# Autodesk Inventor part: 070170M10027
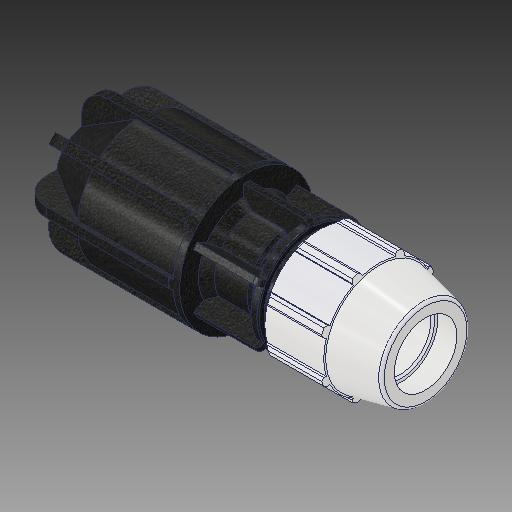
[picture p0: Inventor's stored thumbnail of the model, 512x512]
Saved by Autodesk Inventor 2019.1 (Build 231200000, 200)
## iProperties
Created: 2017-02
Part Number: 070170M10027
Material: PVC-Piping
Description: PLASSON PLASS4 COUPLING 1'' - 0.925
Document SubType Name: Modeling
Designer: KIM
Mass: 92.6774 g
Surface Area: 199.44 cm^2
Volume: 66.1981 cm^3
Density: 1.4 g/cm^3
Appearance: PTFE
Author: KIM
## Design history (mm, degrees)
derived "070170M0.ipt"
feature "Solid1::070170M0.ipt"
tag "TaggingFeature1"
body "Solid1"
other parameters: "d_" = 33.3, "E_" = 62.992, "A_" = 81, "l_" = 70.104, "d_1" = 23.495, "E_1" = 71.12, "l_1" = 85.09, "H_" = 180.086, "d106" = 40.02789, "d2" = 33.3, "d4" = 12.86329, "d5" = 24.5364, "d7" = 62.992, "d8" = 40.02789, "d9" = 11.57143, "d11" = 4.50215, "d12" = 50.3936, "d13" = 120 deg, "d14" = 46.62, "d15" = 12 deg, "d16" = 56.6928, "d18" = 1.665, "d19" = 35 deg, "d20" = 17.5 deg, "d21" = 58.58256, "d23" = 0, "d25" = 360 deg, "d27" = 1.25984, "d42" = 31.5468, "d43" = 1.88976, "d46" = 0.999, "d53" = 0.666, "d67" = 3.1496, "d70" = 29.97, "d71" = 70.104, "d74" = 180 deg, "d75" = 23.495, "d76" = 71.12, "d80" = 29.97, "d84" = 67.564, "d85" = 135 deg, "d86" = 3.556, "d89" = 3.556, "d90" = 135 deg, "d94" = 3.556, "d97" = 5.03936, "d98" = 0, "d100" = 360 deg, "d102" = 78.232, "d103" = 14.224, "d104" = 5.6896, "d105" = 0, "d110" = 85.09, "d112" = 108.0516, "d113" = 28.9306, "d114" = 72.0344, "d115" = 42.672, "d116" = 108.0516, "d117" = 4.2545, "d118" = 31.496, "d119" = 3.1496, "d120" = 0, "d121" = 3.1496, "d123" = 360 deg
